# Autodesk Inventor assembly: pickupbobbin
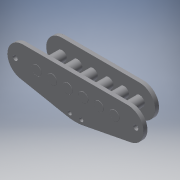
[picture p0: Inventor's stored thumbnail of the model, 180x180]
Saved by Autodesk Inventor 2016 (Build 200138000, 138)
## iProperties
Created: 2016-02
Part Number: pickupbobbin
Document SubType Name: Assembly
Designer: Juha-Pekka
Author: Juha-Pekka
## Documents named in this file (4)
- C:\Users\Juha-Pekka\Desktop\Assignment2\pickupbobbin.iam
- C:\Users\Juha-Pekka\Desktop\Assignment2\Pickup_LowerPlate.ipt
- C:\Users\Juha-Pekka\Desktop\Assignment2\Pickup_UpperPlate.ipt
- C:\Users\Juha-Pekka\Desktop\Assignment2\Pickup_Magnet.ipt
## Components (8 placed, 3 different names)
1. Pickup_LowerPlate:1
2. Pickup_UpperPlate:1
3. Pickup_Magnet:1
4. Pickup_Magnet:2
5. Pickup_Magnet:3
6. Pickup_Magnet:4
7. Pickup_Magnet:5
8. Pickup_Magnet:6
